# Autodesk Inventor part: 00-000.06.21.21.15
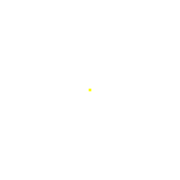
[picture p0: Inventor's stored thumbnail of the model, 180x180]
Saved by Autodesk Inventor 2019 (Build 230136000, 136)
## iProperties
Created: 2019-01
Part Number: 00-000.06.21.21.15
Material: MDF Medium Density Fiberboard
Document SubType Name: Modeling
Designer: m.vorobev
Density: 0.8 g/cm^3
Appearance: Cardboard - Corrugated
Author: m.vorobev
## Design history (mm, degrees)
sketch "Sketch1"
  geometry: L1 (115, 3)-(125, 3); L2 (125, 3)-(125, 0); L3 (125, 0)-(115, 0); L4 (115, 0)-(115, 3); L5 (0, 0)-(29.756, 0); L6 (29.756, 0)-(29.756, 30.712); L7 (29.756, 30.712)-(0, 30.712); L8 (0, 30.712)-(0, 0)
  constraints: 16 end point, 4 parallel, 2 horizontal, 2 perpendicular
  dimensions: "d0" = 250 diameter of L2 L8; "d1" = 230 diameter of L3.end L8; "d2" = 3 distance of L1.end L2.end
revolve "Revolution1" sketch "Sketch1" stored, may be unused: angle "d3" = 90 deg
body "Solid1"
